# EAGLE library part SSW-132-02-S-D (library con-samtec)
THROUGH-HOLE .025" SQ POST SOCKET Source: Samtec SSW.pdf
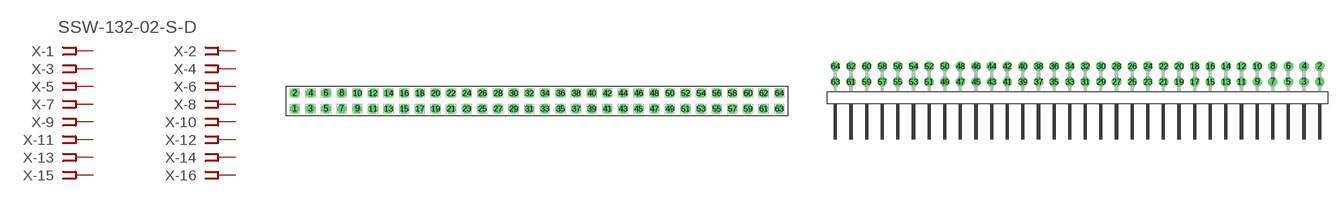
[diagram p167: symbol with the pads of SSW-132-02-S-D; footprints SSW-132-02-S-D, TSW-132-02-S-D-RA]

Designator prefix X; gates -1=FPINV -2=FPIN -3=FPIN -4=FPIN -5=FPIN -6=FPIN -7=FPIN -8=FPIN -9=FPIN -10=FPIN -11=FPIN -12=FPIN -13=FPIN -14=FPIN -15=FPIN -16=FPIN -17=FPIN -18=FPIN -19=FPIN -20=FPIN -21=FPIN -22=FPIN -23=FPIN -24=FPIN -25=FPIN -26=FPIN -27=FPIN -28=FPIN -29=FPIN -30=FPIN -31=FPIN -32=FPIN -33=FPIN -34=FPIN -35=FPIN -36=FPIN -37=FPIN -38=FPIN -39=FPIN -40=FPIN -41=FPIN -42=FPIN -43=FPIN -44=FPIN -45=FPIN -46=FPIN -47=FPIN -48=FPIN -49=FPIN -50=FPIN -51=FPIN -52=FPIN -53=FPIN -54=FPIN -55=FPIN -56=FPIN -57=FPIN -58=FPIN -59=FPIN -60=FPIN -61=FPIN -62=FPIN -63=FPIN -64=FPIN

## SSW-132-02-S-D (MPN: SSW-132-02-S-D; OC_FARNELL: unknown; OC_NEWARK: 11P9837)  [SSW-132-02-S-D]
1  -1:1  pas
2  -2:1  pas
3  -3:1  pas
4  -4:1  pas
5  -5:1  pas
6  -6:1  pas
7  -7:1  pas
8  -8:1  pas
9  -9:1  pas
10  -10:1  pas
11  -11:1  pas
12  -12:1  pas
13  -13:1  pas
14  -14:1  pas
15  -15:1  pas
16  -16:1  pas
17  -17:1  pas
18  -18:1  pas
19  -19:1  pas
20  -20:1  pas
21  -21:1  pas
22  -22:1  pas
23  -23:1  pas
24  -24:1  pas
25  -25:1  pas
26  -26:1  pas
27  -27:1  pas
28  -28:1  pas
29  -29:1  pas
30  -30:1  pas
31  -31:1  pas
32  -32:1  pas
33  -33:1  pas
34  -34:1  pas
35  -35:1  pas
36  -36:1  pas
37  -37:1  pas
38  -38:1  pas
39  -39:1  pas
40  -40:1  pas
41  -41:1  pas
42  -42:1  pas
43  -43:1  pas
44  -44:1  pas
45  -45:1  pas
46  -46:1  pas
47  -47:1  pas
48  -48:1  pas
49  -49:1  pas
50  -50:1  pas
51  -51:1  pas
52  -52:1  pas
53  -53:1  pas
54  -54:1  pas
55  -55:1  pas
56  -56:1  pas
57  -57:1  pas
58  -58:1  pas
59  -59:1  pas
60  -60:1  pas
61  -61:1  pas
62  -62:1  pas
63  -63:1  pas
64  -64:1  pas

## SSW-132-02-S-D-RA (MPN: SSW-132-02-S-D-RA; OC_FARNELL: unknown; OC_NEWARK: 11P9838)  [TSW-132-02-S-D-RA]
Pads as for SSW-132-02-S-D

## Footprint SSW-132-02-S-D (pad centres in mm)
THROUGH-HOLE .025" SQ POST SOCKET Source: Samtec SSW.pdf
drill 1 pad 1.5 octagon: 1 -39.37,-1.27; 2 -39.37,1.27; 3 -36.83,-1.27; 4 -36.83,1.27; 5 -34.29,-1.27; 6 -34.29,1.27; 7 -31.75,-1.27; 8 -31.75,1.27; 9 -29.21,-1.27; 10 -29.21,1.27; 11 -26.67,-1.27; 12 -26.67,1.27; 13 -24.13,-1.27; 14 -24.13,1.27; 15 -21.59,-1.27; 16 -21.59,1.27; 17 -19.05,-1.27; 18 -19.05,1.27; 19 -16.51,-1.27; 20 -16.51,1.27; 21 -13.97,-1.27; 22 -13.97,1.27; 23 -11.43,-1.27; 24 -11.43,1.27; 25 -8.89,-1.27; 26 -8.89,1.27; 27 -6.35,-1.27; 28 -6.35,1.27; 29 -3.81,-1.27; 30 -3.81,1.27; 31 -1.27,-1.27; 32 -1.27,1.27; 33 1.27,-1.27; 34 1.27,1.27; 35 3.81,-1.27; 36 3.81,1.27; 37 6.35,-1.27; 38 6.35,1.27; 39 8.89,-1.27; 40 8.89,1.27; 41 11.43,-1.27; 42 11.43,1.27; 43 13.97,-1.27; 44 13.97,1.27; 45 16.51,-1.27; 46 16.51,1.27; 47 19.05,-1.27; 48 19.05,1.27; 49 21.59,-1.27; 50 21.59,1.27; 51 24.13,-1.27; 52 24.13,1.27; 53 26.67,-1.27; 54 26.67,1.27; 55 29.21,-1.27; 56 29.21,1.27; 57 31.75,-1.27; 58 31.75,1.27; 59 34.29,-1.27; 60 34.29,1.27; 61 36.83,-1.27; 62 36.83,1.27; 63 39.37,-1.27; 64 39.37,1.27

## Footprint TSW-132-02-S-D-RA (pad centres in mm)
THROUGH-HOLE .025" SQ POST HEADER Source: Samtec TSW.pdf
drill 1 pad 1.5 octagon: 1 39.37,1.524; 2 39.37,4.064; 3 36.83,1.524; 4 36.83,4.064; 5 34.29,1.524; 6 34.29,4.064; 7 31.75,1.524; 8 31.75,4.064; 9 29.21,1.524; 10 29.21,4.064; 11 26.67,1.524; 12 26.67,4.064; 13 24.13,1.524; 14 24.13,4.064; 15 21.59,1.524; 16 21.59,4.064; 17 19.05,1.524; 18 19.05,4.064; 19 16.51,1.524; 20 16.51,4.064; 21 13.97,1.524; 22 13.97,4.064; 23 11.43,1.524; 24 11.43,4.064; 25 8.89,1.524; 26 8.89,4.064; 27 6.35,1.524; 28 6.35,4.064; 29 3.81,1.524; 30 3.81,4.064; 31 1.27,1.524; 32 1.27,4.064; 33 -1.27,1.524; 34 -1.27,4.064; 35 -3.81,1.524; 36 -3.81,4.064; 37 -6.35,1.524; 38 -6.35,4.064; 39 -8.89,1.524; 40 -8.89,4.064; 41 -11.43,1.524; 42 -11.43,4.064; 43 -13.97,1.524; 44 -13.97,4.064; 45 -16.51,1.524; 46 -16.51,4.064; 47 -19.05,1.524; 48 -19.05,4.064; 49 -21.59,1.524; 50 -21.59,4.064; 51 -24.13,1.524; 52 -24.13,4.064; 53 -26.67,1.524; 54 -26.67,4.064; 55 -29.21,1.524; 56 -29.21,4.064; 57 -31.75,1.524; 58 -31.75,4.064; 59 -34.29,1.524; 60 -34.29,4.064; 61 -36.83,1.524; 62 -36.83,4.064; 63 -39.37,1.524; 64 -39.37,4.064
